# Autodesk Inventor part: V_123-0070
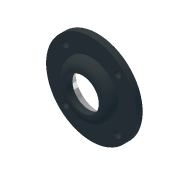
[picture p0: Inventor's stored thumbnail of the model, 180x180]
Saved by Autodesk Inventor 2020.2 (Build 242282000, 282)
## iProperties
Created: 2006-03
Part Number: V_123-0070
Document SubType Name: Modeling
Designer: F.Stasiak
Description: Pokrywka typ 2
Material: St 4S
Project: Przekładnia X51
Mass: 155.323 g
Surface Area: 100.762 cm^2
Volume: 19.7864 cm^3
Density: 7.85 g/cm^3
Appearance: Brąz armatni (nowy/polerowany)
Manager: www.cadconsulting.pl
Company: Fabian Stasiak CAD Consulting
Author: F.Stasiak
Subject: Zbiór ćwiczeń. Autodesk Inventor 2020. Kurs podstawowy
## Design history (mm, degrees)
sketch "Szkic1"
  geometry: L1 (17.5, 0)-(17.5, -7); L2 (17.5, -7)-(13, -7); L3 (13, -7)-(13, -12); L4 (36, 0)-(17.5, 0); L5 (0, -12)-(0, 0); L6 (13, -12)-(15, -12); L7 (22, -5)-(36, -5); L8 (36, -5)-(36, 0); L9 (22, -5)-(17.5, -5); L10 (13, -12)-(0, -12); L11 (17.5, 0)-(0, 0); A1 r 7 centre (15, -5) between (15, -12) and (22, -5); 1 further point
  constraints: 22 end point, 5 perpendicular, 4 parallel, 2 point on circle, 2 point on line, 1 centre point, 1 coincident, 1 horizontal, 1 tangent, 1 vertical
  dimensions: "d0" = 35 diameter of L1 L5; "d1" = 26 diameter of L3 L5; "d3" = 72 diameter of L8 L5; "d4" = 7 distance of L1.start L1.end; "d5" = 5 distance of L7.end L4.start; "d6" = 12 distance between parallel lines of L6 L4; "d13" = 14 distance from line of L7.start L8
revolve "Obrót1" sketch "Szkic1" stored, may be unused: angle "d14" = 90 deg
sketch "Szkic2" dims "d16" = 59
  geometry: L1 (0, 0)-(-25.456, -25.456); L2 (0, 0)-(0, -36); A1 r 36 centre (0, 0) between (-25.456, -25.456) and (0, -36) reference; 3 further points
  constraints: 4 end point, 2 point on circle, 1 coincident, 1 point on line, 1 vertical, 3 other
  dimensions: "d15" = 45 deg angle of L2 L1
hole "Otwór1" sketch "Szkic2" at (-20.86, -20.86) diameter "d17" = 5.5; stored, may be unused: countersink angle "d21" = 90 deg, drill point angle "d23" = 118 deg; dims "d18" = 6, "d19" = 4, "d20" = 2, "d22" = 8
pattern_circular "Szyk kołowy1" dims angle "d25" = 360 deg
node "Bryła1"
node "Korpusy bryłowe"
node "Korpusy powierzchniowe"
